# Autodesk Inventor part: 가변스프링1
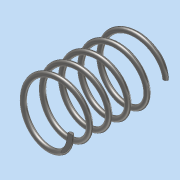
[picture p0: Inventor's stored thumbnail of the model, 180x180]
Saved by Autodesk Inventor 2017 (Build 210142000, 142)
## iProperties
Part Number: 가변스프링1
Material: 강철, 연강
Document SubType Name: Modeling
Designer: MRC
Density: 7.85 g/cm^3
Appearance: 반연마
Mass: 8.42502 g
Surface Area: 21.7259 cm^2
Volume: 1.07325 cm^3
Author: MRC
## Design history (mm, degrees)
sketch "스케치1"
  geometry: L1 (0, 0)-(11, 0); L2 (11, 0)-(11, 37.411); L3 (11, 37.411)-(0, 37.411); L4 (0, 37.411)-(0, 0); C1 r 1 at (11, 0)
  constraints: 8 end point, 2 parallel, 1 centre point, 1 coincident, 1 horizontal, 1 perpendicular
  dimensions: "d0" = 22 diameter of L2 L4; "d1" = 2 diameter of C1; "d2" = 37.4112 distance between parallel lines of L1 L3 (derived)
feature "코일1" sketch "스케치1" pitch "d3" = 10; turns "d5" = 5; dims "d4" = 37.4112 (= d2), "d6" = 0, angle "d7" = 90 deg, angle "d8" = 90 deg, "d9" = 0, "d10" = 0
sketch "스케치2"
  geometry: L1 (-25.076, 37.411)-(25.076, 37.411); L2 (25.076, 37.411)-(25.076, 0); L3 (25.076, 0)-(-25.076, 0); L4 (-25.076, 0)-(-25.076, 37.411); L5 (0, 37.411)-(0, 0) reference; 2 further points
  constraints: 8 end point, 2 midpoint, 2 parallel, 1 coincident, 1 horizontal, 1 perpendicular
  dimensions: "d11" = 50.15108 distance of L1.start L1.end
extrude "돌출1" sketch "스케치2" stored distance "d12" = 0; taper "d13" = 0 deg
node "솔리드1"
